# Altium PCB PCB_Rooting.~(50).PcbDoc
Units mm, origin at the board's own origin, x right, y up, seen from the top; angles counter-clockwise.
Board outline 68.5 x 51 mm, 4 copper layers (Top Layer, Mid-Layer 1, Mid-Layer 2, Bottom Layer); 59 components, 42 nets, 192 pads, 55 vias.
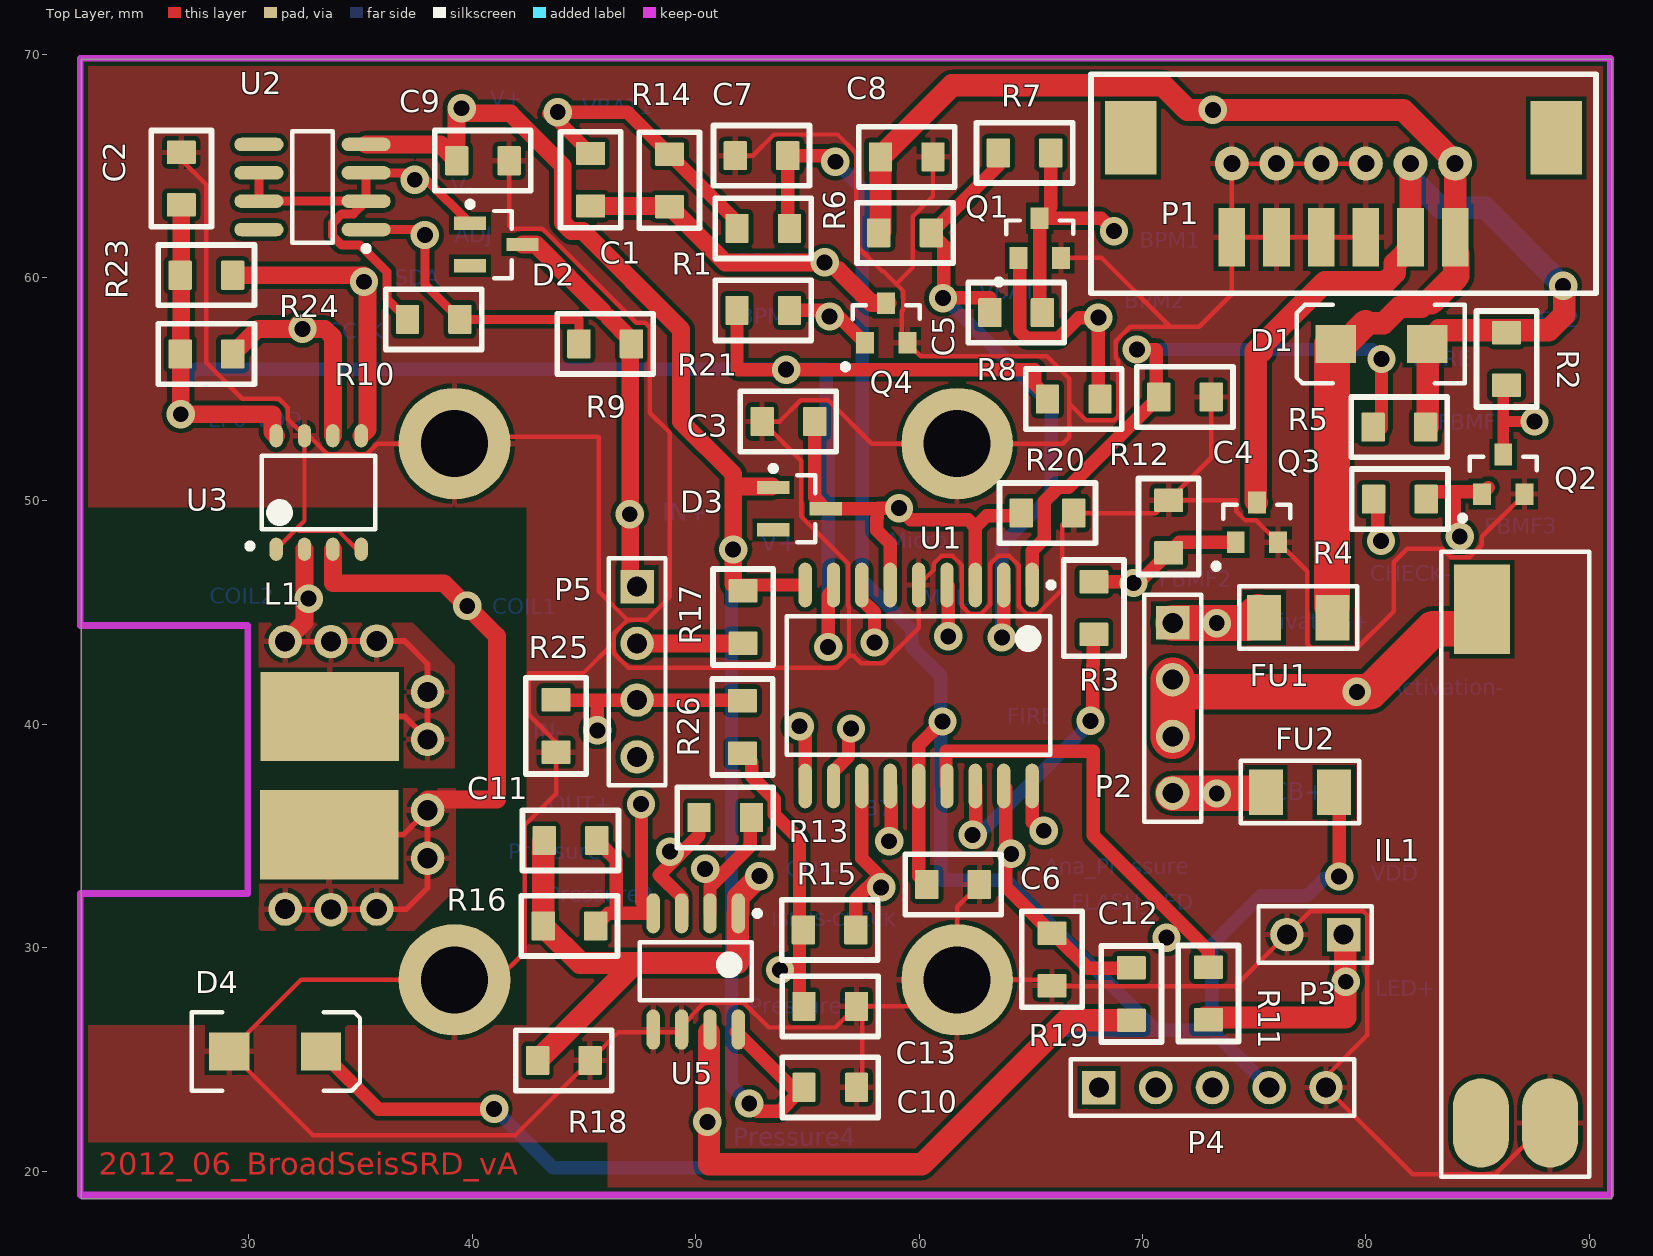
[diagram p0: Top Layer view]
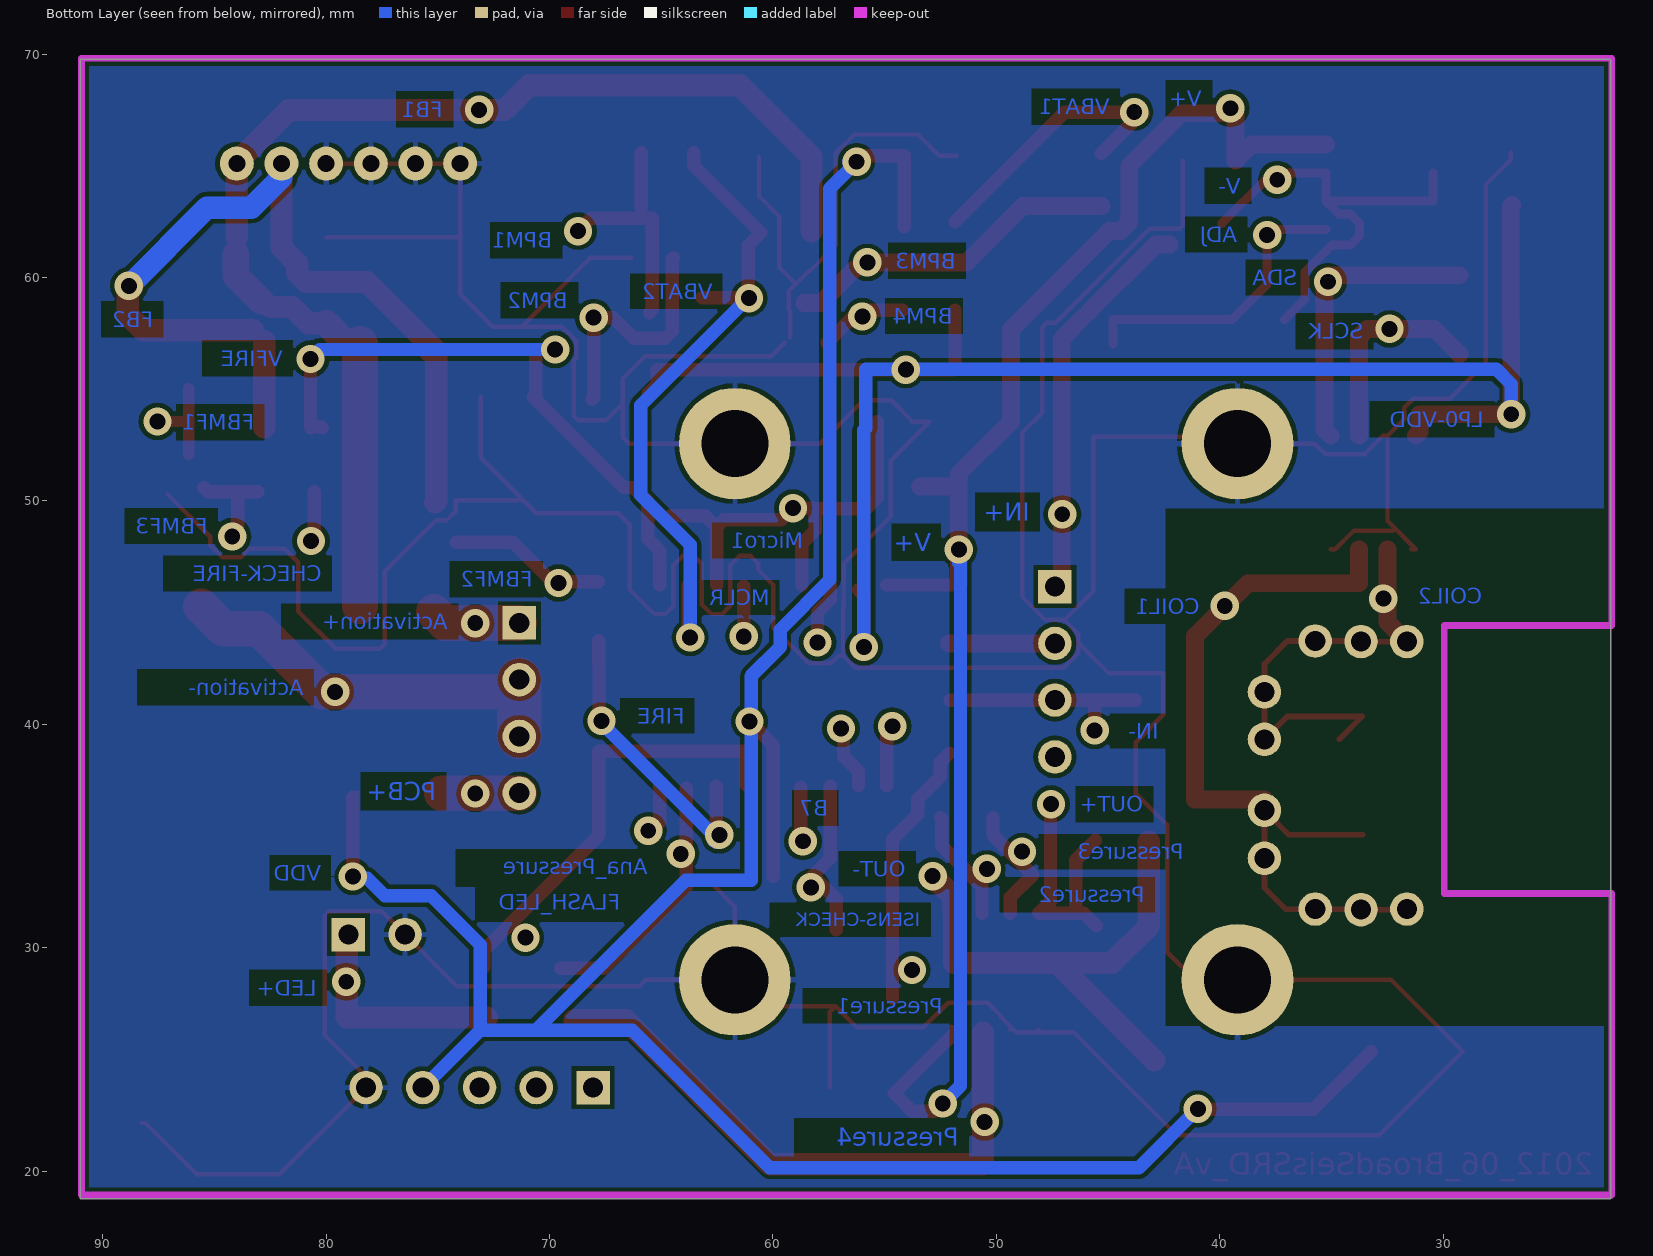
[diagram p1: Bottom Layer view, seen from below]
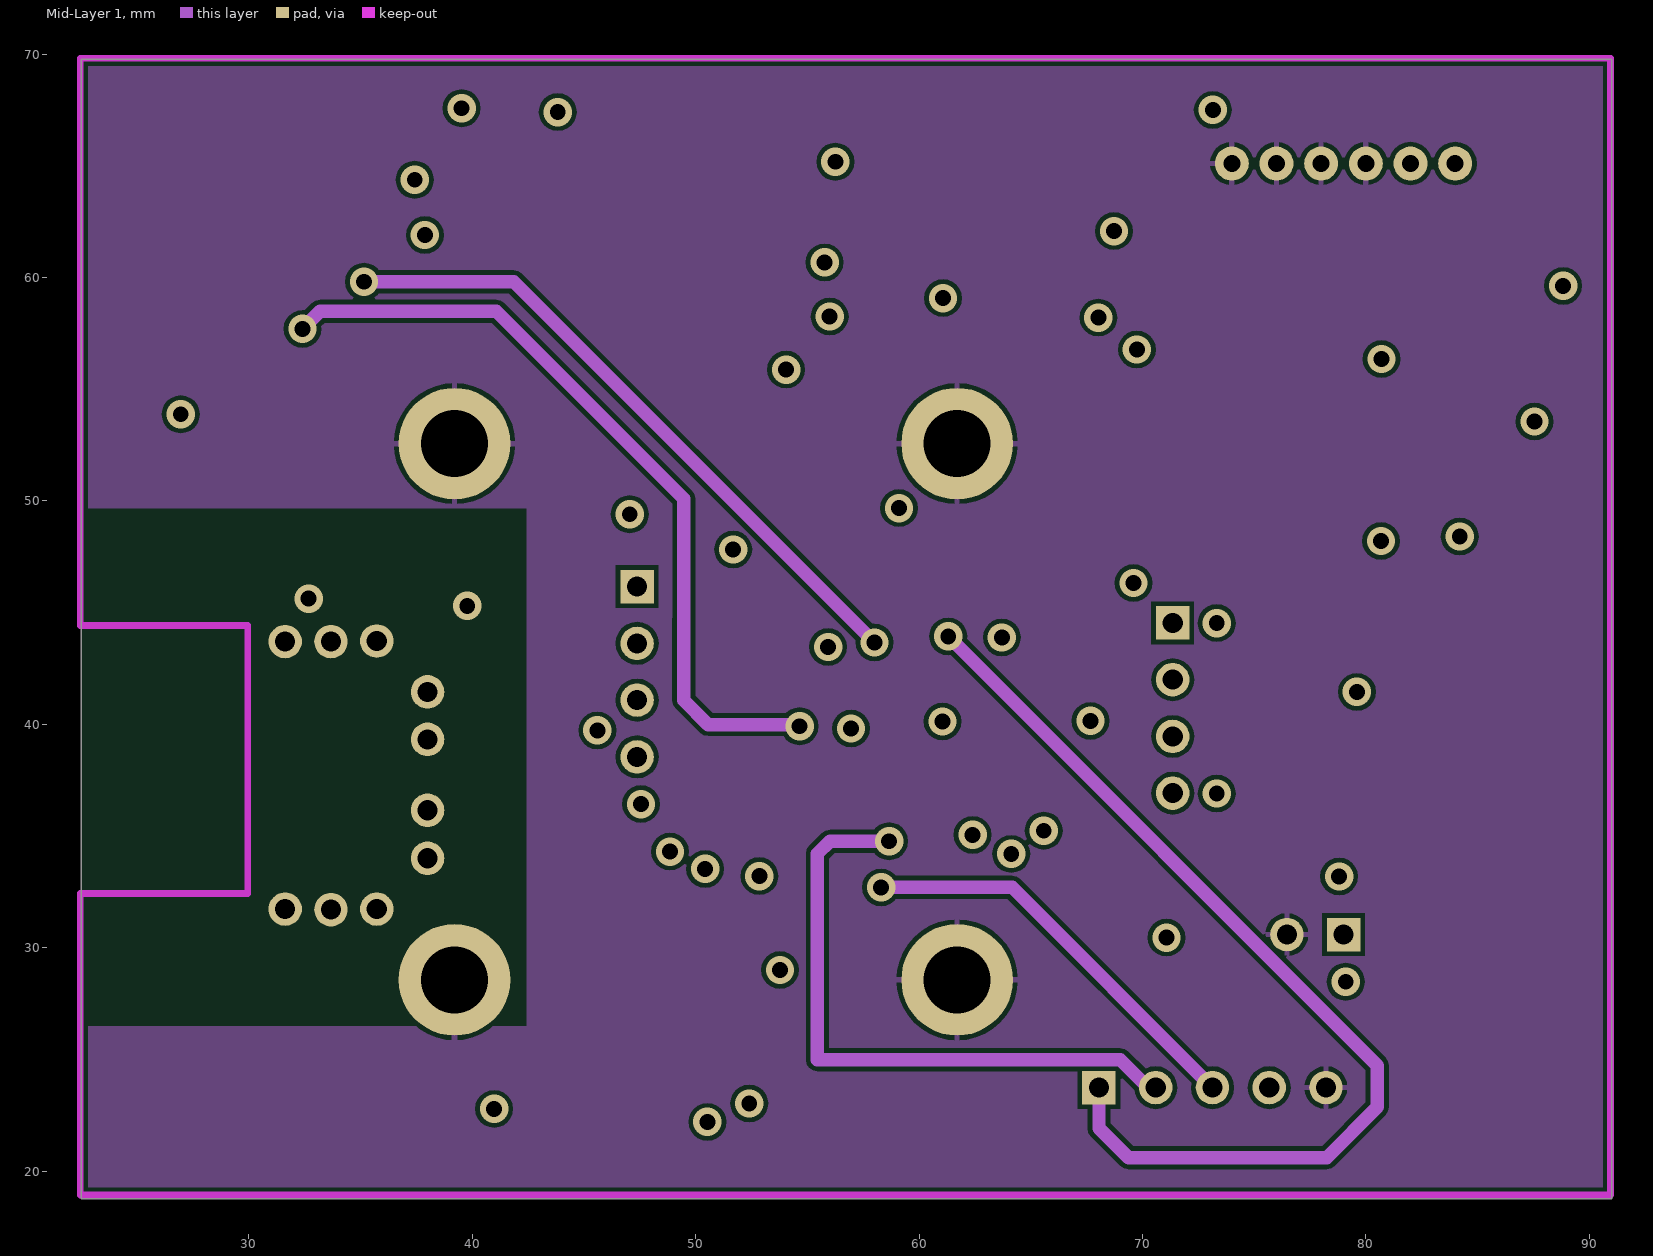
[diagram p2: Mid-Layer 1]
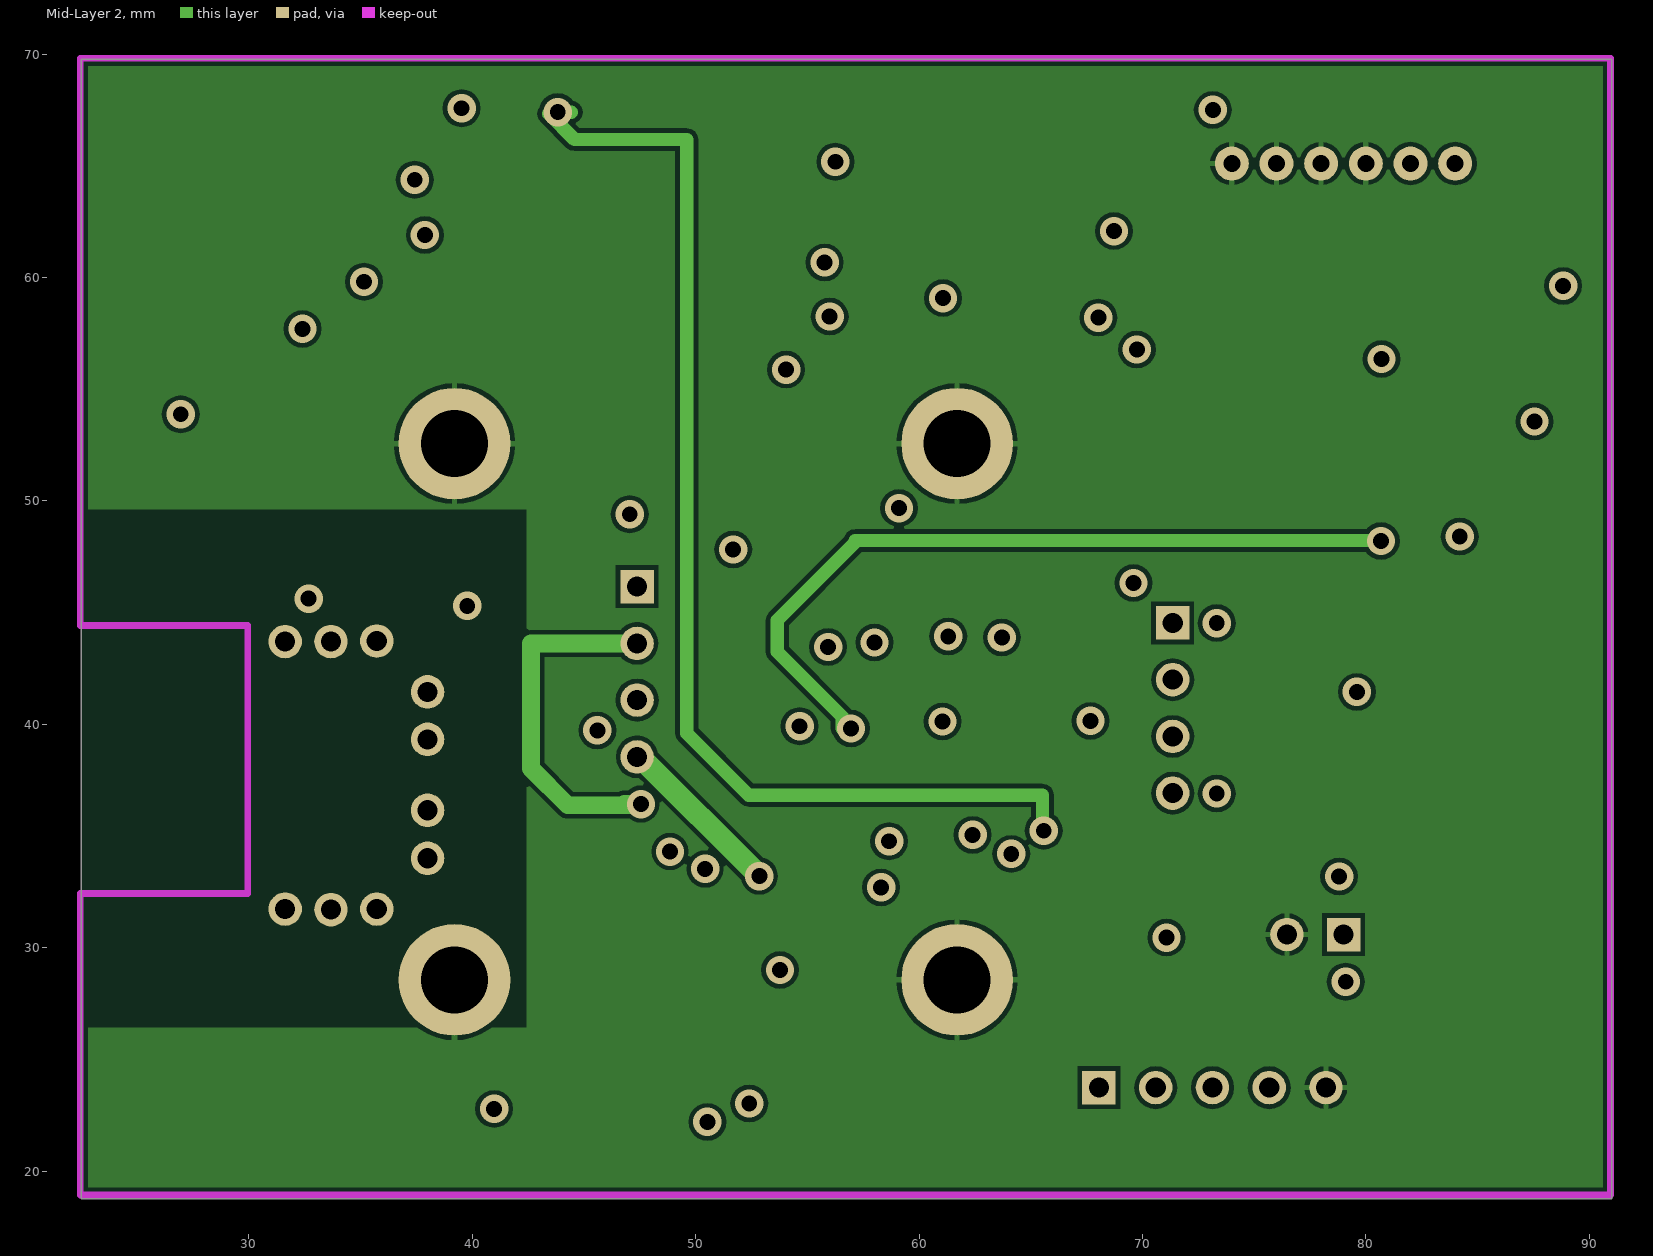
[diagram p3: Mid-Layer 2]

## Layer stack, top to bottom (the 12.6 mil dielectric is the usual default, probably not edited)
Top Layer: signal copper 0.0356
Dielectric: dielectric 0.32, FR-4, Dk 4.8
Mid-Layer 1: signal copper 0.0356
Dielectric: dielectric 0.32, FR-4, Dk 4.8
Mid-Layer 2: signal copper 0.0356
Dielectric: dielectric 0.32, FR-4, Dk 4.8
Bottom Layer: signal copper 0.0356

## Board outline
22.505,18.76 91.005,18.76 91.005,69.76 22.505,69.76

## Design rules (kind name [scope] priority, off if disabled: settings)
Clearance [All] p1: gap=0.2
HoleSize [All] p1: absolutevalues=TRUE maxlimit=5 minlimit=0.025 maxpercent=80.000 minpercent=20.000
PolygonConnect [All] p1: connectstyle=Relief reliefconductorwidth=0.254 reliefentries=4 polygonreliefangle="90 Angle"
RoomDefinition PCB_Schematics [InComponentClass('PCB_Schematics')] p1: confinementstyle=ConfineIn formatcopy=TRUE lockcomponents=FALSE outline 0,0 106.55,0 106.55,84.8 0,84.8
RoutingVias [All] p1: holewidth=0.6 width=1 viastyle="Through Hole" minholewidth=0.711 minwidth=1.27 maxholewidth=0.711 maxwidth=1.27
SilkscreenOverComponentPads [All] p1: minsilkscreentomaskgap=0.254
SolderMaskExpansion [All] p1: expansion=0.102
Width [All] p1: maxlimit=2 minlimit=0.2 preferedwidth=0.6
26 further rules are at their usual default settings.

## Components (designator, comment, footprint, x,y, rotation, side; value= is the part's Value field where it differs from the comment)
C1 "" 1608[0603] 45.3,64.375 r90 top
C2 "" 1608[0603] 26.975,64.425 r270 top
C3 "" 1608[0603] 54.15,53.55 r0 top
C4 "" 1608[0603] 71.9,54.65 r180 top
C5 "" 1608[0603] 64.35,58.425 r180 top
C6 "" 1608[0603] 61.525,32.825 r180 top
C7 "" 1608[0603] 52.95,65.45 r0 top
C8 "" 1608[0603] 59.45,65.4 r180 top
C9 "" 1608[0603] 40.475,65.225 r180 top
C10 "" 1608[0603] 56.025,23.75 r180 top
C11 "" 1608[0603] 44.4,34.8 r0 top
C12 "" 1608[0603] 65.95,29.475 r90 top
C13 "" 1608[0603] 56.025,27.375 r180 top
D1 "" DiodeRS1D(recommendedfootprint) 80.7,57.025 r180 top
D2 "" SOT-23_M 41.075,61.475 r0 top
D3 "" SOT-23_M 54.65,49.65 r0 top
D4 "" DiodeRS1D(recommendedfootprint) 31.175,25.35 r0 top
FU1 "1A" FU(recommendedfootprint) 76.975,44.775 r0 top
FU2 "200mA" FU(recommendedfootprint) 77.055,36.96 r180 top
IL1 "ILS" ILS 88.15,45.15 r270 top
L1 "" INDC4532 33.625,37.7 r270 top
P1 "ConnectorToFB" "HIROSE DF3DZ 6P-2V" 79,63.1 r0 top
P2 "Battery Pack pigtail" HDR1X4 71.355,44.535 r270 top
P3 "Connector to LED" HDR1X2 79.005,30.585 r180 top
P4 "Connector to Prog." HDR1X5 68.055,23.735 r0 top
P5 "Pressure Transducer pigtail" HDR1X4 47.38,46.16 r270 top
Q1 "" transistor_SOT-23(recommendedfootprint) 65.4,61.85 r90 top
Q2 "" transistor_SOT-23(recommendedfootprint) 86.15,51.275 r90 top
Q3 "" transistor_SOT-23(recommendedfootprint) 75.125,49.125 r90 top
Q4 "" transistor_SOT-23(recommendedfootprint) 58.525,58.05 r90 top
R1 "" J1-0603 53.025,62.2 r0 top
R2 "" J1-0603 86.3,56.35 r90 top
R3 "" J1-0603 67.825,45.2 r90 top
R4 "" J1-0603 81.525,50.075 r0 top
R5 "" J1-0603 81.5,53.3 r0 top
R6 "" J1-0603 59.375,62 r180 top
R7 "" J1-0603 64.725,65.575 r180 top
R8 "" J1-0603 66.925,54.55 r0 top
R9 "" J1-0603 45.95,57.025 r0 top
R10 "" J1-0603 38.275,58.125 r180 top
R11 "" J1-0603 72.95,27.95 r90 top
R12 "" J1-0603 71.175,48.85 r270 top
R13 "" J1-0603 51.325,35.825 r0 top
R14 "" J1-0603 48.825,64.35 r90 top
R15 "" J1-0603 56,30.8 r180 top
R16 "" J1-0603 44.35,30.975 r0 top
R17 "" J1-0603 52.125,44.8 r90 top
R18 "" 1608[0603] 44.1,24.95 r180 top
R19 "" J1-0603 69.5,27.925 r90 top
R20 "" J1-0603 65.75,49.45 r180 top
R21 "" J1-0603 53.025,58.525 r0 top
R23 "" J1-0603 28.1,60.1 r0 top
R24 "" J1-0603 28.1,56.575 r180 top
R25 "" J1-0603 43.75,39.925 r90 top
R26 "" J1-0603 52.1,39.875 r90 top
U1 "PIC16LF1827-I/SO" SOIC-SO18_L 59.98,41.735 r270 top
U2 "LM334D" SO8_N 32.85,64.05 r180 top
U3 "M24LR64" SO8N_N 33.125,50.375 r90 top
U5 "AD620BR" R-8D_N 50.005,28.935 r270 top

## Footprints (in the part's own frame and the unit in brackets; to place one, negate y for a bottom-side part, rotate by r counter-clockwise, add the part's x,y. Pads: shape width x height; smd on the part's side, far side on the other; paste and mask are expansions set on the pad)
1608[0603] [mm] "Chip Capacitor, Body 1.6x0.8mm, IPC High Density"
  rrect10% 1.05x1.3 smd: 1(-1.175,0) 2(1.175,0)
  silkscreen extent -2.15,-1.35 2.15,1.35
DiodeRS1D(recommendedfootprint) [mm] "DO-214-AB/SMC; 2 C-Bend Leads; Body 7.9 x 5.9 mm, inc. leads (LxW)"
  rect 1.8x1.7 smd: 1(-2.05,0) 2(2.05,0)
  silkscreen extent -3.73,-1.75 3.8,1.75
FU(recommendedfootprint) [mm] "Thru-Hole; 2 Leads"
  rect 1.52x2.03 smd: 1(-1.525,0) 2(1.525,0)
  silkscreen extent -2.65,-1.4 2.65,1.4
HDR1X2 [mm] "Connector; Header; 2 Position"
  rect 1.5x1.5 hole 0.9: 1(0,0)
  round 1.5 hole 0.9: 2(2.54,0)
  silkscreen extent -1.27,-1.27 3.81,1.27
HDR1X4 [mm] "Connector; Header; 4 Position"
  rect 1.5x1.5 hole 0.9: 1(0,0)
  round 1.5 hole 0.9: 2(2.54,0) 3(5.08,0) 4(7.62,0)
  silkscreen extent -1.27,-1.27 8.89,1.27
HDR1X5 [mm] "Connector; Header; 5 Position"
  rect 1.5x1.5 hole 0.9: 1(0,0)
  round 1.5 hole 0.9: 2(2.54,0) 3(5.08,0) 4(7.62,0) 5(10.16,0)
  silkscreen extent -1.27,-1.27 11.43,1.27
"HIROSE DF3DZ 6P-2V" [mm]
  rect 2.3x3.3 smd: 0(-9.52,3.15) 0(9.52,3.15)
  rect 1.2x2.6 smd: 1(-5,-1.3) 2(-3,-1.3) 3(-1,-1.3) 4(1,-1.3) 5(3,-1.3) 6(5,-1.3)
  round 1.524 hole 0.762: 1(-5,2) 2(-3,2) 3(-1,2) 4(1,2) 5(3,2) 6(5,2)
  silkscreen extent -11.3,-3.8 11.3,6
ILS [mm]
  rect 4x2.5 smd: 1(0,-2.95)
  oval 4x2.5 smd: 2(23,-3) 3(23,0.1)
  silkscreen extent -2.58,-4.77 25.4,1.85
INDC4532 [mm] "Chip Inductor, Body 4.5x3.2mm, IPC High Density"
  round 1.5 hole 0.9: 1(-6.025,2.1) 1(-6,0.05) 1(-6,-2) 1(-3.75,4.375) 1(-1.625,4.375) 2(1.55,4.375) 2(3.7,4.375) 2(5.975,2.1) 2(5.975,-2) 2(6,0.05)
  rect 4x6.2 smd: 1(-2.65,0) 2(2.65,-0.025)
  Top Layer lines w0.254: -6,-2 -6,0.05 -6.025,0.075 -6.025,2.1 -6.025,3.35 -5,4.375 -3.75,4.375 -1.625,4.375 -2.65,3.35 -2.65,0 -1.625,1.025
J1-0603 [mm] "Chip Capacitor, Body 1.6x0.8mm, IPC High Density"
  rrect10% 1.05x1.3 smd: 1(-1.175,0) 2(1.175,0)
  silkscreen extent -2.15,-1.35 2.15,1.35
R-8D_N [mm] "SOIC, 8-Leads, Body 4.9x3.9mm, Pitch 1.27mm, IPC Medium Density"
  oval 1.8x0.6 smd: 1(-2.6,1.905) 2(-2.6,0.635) 3(-2.6,-0.635) 4(-2.6,-1.905) 5(2.6,-1.905) 6(2.6,-0.635) 7(2.6,0.635) 8(2.6,1.905)
  silkscreen extent -2.72,-2.5 1.3,2.88, body extent -2,-2.5 2,2.5, height 2.59
SO8_N [mm] "SOIC, 8-Leads, Body 4.9x3.9mm, Pitch 1.27mm, IPC Medium Density"
  oval 2.2x0.6 smd: 1(-2.4,1.905) 2(-2.4,-0.635) 2(-2.4,0.635) 2(2.4,-0.635) 2(2.4,0.635) 4(-2.4,-1.905) 5(2.4,-1.905) 8(2.4,1.905)
  silkscreen extent -2.53,-2.5 0.9,2.88, body extent -1.95,-2.45 1.95,2.45, height 1.75
SO8N_N [mm] "SOP, 8-Leads, Body 5.3x5.3mm, Pitch 1.27mm, IPC Medium Density"
  oval 1.04x0.6 smd: 1(-2.54,1.905) 2(-2.54,0.635) 3(-2.54,-0.635) 4(-2.54,-1.905) 5(2.54,-1.905) 6(2.54,-0.635) 7(2.54,0.635) 8(2.54,1.905)
  silkscreen extent -2.52,-2.54 1.65,3.2, body extent -2.29,-2.54 2.29,2.54, height 2.13
SOIC-SO18_L [mm] "SOIC, 18-Leads, Body 11.5x7.5mm, Pitch 1.27mm, IPC High Density"
  oval 2x0.6 smd: 1(-4.5,5.08) 2(-4.5,3.81) 3(-4.5,2.54) 4(-4.5,1.27) 5(-4.5,0) 6(-4.5,-1.27) 7(-4.5,-2.54) 8(-4.5,-3.81) 9(-4.5,-5.08) 10(4.5,-5.08) 11(4.5,-3.81) 12(4.5,-2.54) 13(4.5,-1.27) 14(4.5,0) 15(4.5,1.27) 16(4.5,2.54) 17(4.5,3.81) 18(4.5,5.08)
  silkscreen extent -4.62,-5.9 3.1,6.06, body extent -3.8,-5.95 3.8,5.95, height 2.65
SOT-23_M [mm] "SOT23, 3-Leads, Body 2.9x1.3mm, Pitch 0.95mm, Lead Span 2.5mm, IPC Low Density"
  rect 1.45x0.6 smd: 1(-1.175,0.95) 2(-1.175,-0.95) 3(1.175,0)
  silkscreen extent -1.3,-1.5 0.7,1.92, body extent -0.7,-1.5 0.7,1.5, height 1.1
transistor_SOT-23(recommendedfootprint) [mm] "SOT23, 3-Leads, Body 2.9x1.3mm, Pitch 0.95mm, Lead Span 2.5mm, IPC Low Density"
  rect 0.972x0.802 smd: 1(-0.975,0.95) 2(-0.975,-0.95) 3(0.8,0)
  silkscreen extent -2.17,-1.5 0.7,1.95, body extent -0.7,-1.5 0.7,1.5, height 1.1

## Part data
C1 C2 C3 C4 C5 C6 C7 C8 C9 C10 C11 C12 C13: library part "Cap Semi", "Capacitor (Semiconductor SIM Model)"
D1 D4: library part Diode, "Default Diode"
D2 D3: library part "Diode BAS16", "Silicon Switching Diode for High-Speed Switching"
FU1 FU2: library part "Fuse 1", "Fuse"
IL1: "SPDT Subminiature Toggle Switch, Right Angle Mounting, Vertical Actuation"
L1: library part Inductor, "Inductor"
P1: "Header, 6-Pin"
P2 P5: "Header, 4-Pin"
P3: "Header, 2-Pin"
P4: "Header, 5-Pin"
Q1 Q2 Q4: library part NPN, "NPN Bipolar Transistor"
Q3: library part MOSFET-IRLML, "N-Channel MOSFET"
R1 R2 R3 R4 R5 R6 R7 R8 R9 R10 R11 R12 R13 R14 R15 R16 R17 R18 R19 R20 R21 R23 R24 R25 R26: library part Res3, "Resistor"
U1: "EPROM-Based 8-Bit CMOS Microcontroller, 25 Bytes RAM, 4 MHz, 18-Pin SOIC, 3.0 to 5.5V Supply Range, Extended Temperature"
U2: "Three Terminal Adjustable Current Source"
U3: "32 Kbit Serial I²C Bus EEPROM"
U5: "Low-Cost, Low-Power Instrumentation Amplifier"

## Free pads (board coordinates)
  round 5 hole 3: 1(39.205,28.56) 1(39.205,52.56) 1(61.705,28.56) 1(61.705,52.56)

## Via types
v1: diameter 1.27, hole 0.711, Top Layer to Bottom Layer, 55 vias

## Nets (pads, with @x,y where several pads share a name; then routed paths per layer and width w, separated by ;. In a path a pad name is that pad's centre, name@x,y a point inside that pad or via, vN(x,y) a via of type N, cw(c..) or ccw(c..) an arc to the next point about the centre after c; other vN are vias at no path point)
ACTIVATION+: FU1.1 P2.1 | length 4
  Top Layer w1.6: P2.1 74.68,44.535 FU1.1@75.185,45.04
  other v1: 73.325,44.525
ACTIVATION-: IL1.1 P2.2 P2.3 | length 18.6
  Top Layer w0.2: P2.2 71.89,41.46
  Top Layer w1.6: 71.89,41.46 80.185,41.46 83.005,44.28 84.605,44.28 IL1.1@85.6,45.275
  Top Layer w2: P2.3 P2.2
  other v1: 79.6,41.45
ADJ: R9.1 R10.1 U2.1 | length 13.6
  Top Layer w0.4: U2.1 37.635,62.145 v1(37.88,61.9) 37.88,59.695 R10.1 44.76,58.125 ; R9.1 44.775,58.11
ANA_PRESSURE: C12.2 R19.2 U1.17 | length 11.4
  Top Layer w0.2: U1.17 U1.17@63.88,37.145 ; v1@63.88,33.66 v1@63.905,33.685
  Top Layer w0.6: U1.17@63.88,37.145 63.88,33.66 63.88,32.72 C12.2 ; C12.2@66.2,30.45 67.575,29.075 R19.2@69.5,29.075
  other v1: 64.125,34.2
B7: P4.2 U1.13 | length 30.8
  Top Layer w0.2: U1.13 U1.13@58.755,37.19
  Top Layer w0.6: v1(58.659,34.764) 58.659,35.014 58.755,35.11 U1.13@58.755,37.19
  Mid-Layer 1 w0.6: v1(58.659,34.764) 56.014,34.764 55.45,34.2 55.45,24.985 69.012,24.985 70.262,23.735 P4.2
BPM1: C5.1 Q1.3 R7.1 | length 10.3
  Top Layer w0.6: C5.1 65.4,58.55 Q1.3 68.15,62.65 v1(68.725,62.075) ; 65.9,63.15 R7.1
BPM2: Q1.1 R8.2 | length 11.5
  Top Layer w0.6: Q1.1 64.5,60.825 64.5,57.599 64.824,57.275 66.226,57.275 67.151,58.2 v1(68.025,58.2) v1@68.325,58.2 ; v1@68.025,58.4 68.025,54.625 R8.2
BPM3: C1.1 Q4.3 R14.1 | length 14.3
  Top Layer w0.8: C1.1 R14.1@48.8,63.2 ; R14.1 51.325,60.675 v1(55.775,60.675) ; 56.387,60.337 57.875,58.85 Q4.3@58.6,58.85
BPM4: Q4.1 R21.2 | length 4
  Top Layer w0.6: R21.2 56.125,58.525 Q4.1
  other v1: 56,58.25
CHECK-FIRE: R4.1 U1.11 | length 40.5
  Top Layer w0.2: v1@56.84,39.695 v1(56.955,39.81)
  Top Layer w0.6: U1.11 56.17,37.9 56.84,38.57 v1@56.84,39.695 ; R4.1@80.525,50.4 80.525,48.225 80.675,48.075 80.675,48.001 80.679,48.001 v1(80.679,48.202)
  Mid-Layer 2 w0.6: v1@56.565,39.81 56.565,40.335 53.65,43.25 53.65,44.65 57.15,48.15 57.15,48.225 80.525,48.225 80.675,48.075 80.675,48.001 80.679,48.001 v1(80.679,48.202)
COIL1: L1.2 U3.3 | length 35.4
  Top Layer w0.254: L1.2@31.65,31.7 L1.2@33.675,31.7 ; L1.2@33.6,35.05 36.9,35.05 38,36.15 38,34 38,32.675 37.05,31.725 35.725,31.725 L1.2@33.7,31.725
  Top Layer w0.6: L1.2@31.625,31.725 L1.2@31.65,31.7 ; L1.2@33.675,31.7 L1.2@33.7,31.725
  Top Layer w0.8: U3.3 33.76,46.31 38.735,46.31 41.1,43.945 41.1,36.625 L1.2@38,36.625
  other v1: 39.775,45.3
COIL2: L1.1 U3.2 | length 4.5
  Top Layer w0.8: L1.1@31.625,43.7 32.49,44.565 U3.2
  other v1: 32.675,45.625
FB1: C8.2 D1.2 FU1.2 P1.6 R6.2 | length 53.6
  Top Layer w1: R6.2@58.275,62.075 C8.2 61.475,68.6 70.92,68.6 72.02,67.5 v1(73.15,67.5) 81.668,67.5 84,65.168 84,65.1 P1.6@84,61.8 ; 79.988,57.95 80.794,57.95 81.519,58.675 82.477,58.675
  Top Layer w1.2: D1.2@79.063,57.025 79.988,57.95 ; 82.91,58.935 84.05,60.075 P1.6@84.05,61.05
  Top Layer w1.6: FU1.2@78.48,45.285 D1.2@78.48,57.025
FB2: D1.1 P1.5 Q3.3 R2.2 R5.2 | length 40.4
  Top Layer w1: Q3.3 75.075,49.975 75.075,56.7 ; 75.335,56.7 75.075,56.7 ; P1.5@82,65.1 82,61.8 82,61.335 81.3,60.635 81.3,60.21 80.89,59.8 78.175,59.8 75.075,56.7 ; R5.2@82.775,53.3 D1.1@82.775,57.15 ; D1.1@83.275,57.635 88.185,57.635 88.875,58.325 v1@88.875,59.65
  Bottom Layer w1: P1.5@82,65.1 82,64.475 83.35,63.125 85.332,63.125 v1(88.832,59.625)
FBMF1: Q2.3 R2.1 | length 4.7
  Top Layer w0.2: Q2.3 Q2.3@86.3,52.225
  Top Layer w0.5: Q2.3 86.15,53.55 ; R2.1@86.15,55.025 86.15,53.55 ; v1@87.725,53.55 86.15,53.55
  other v1: 87.55,53.55
FBMF2: Q3.1 R3.2 R12.2 | length 7.1
  Top Layer w0.6: R3.2 69.875,46.375 R12.2 71.65,48.15 Q3.1
  other v1: 69.6,46.325
FBMF3: Q2.1 R4.2 | length 4.7
  Top Layer w0.6: R4.2@83.05,50.4 83.925,50.4 ; v1(84.204,48.402) 84.254,48.402 84.257,48.405 84.257,48.568 83.95,48.875 83.95,50.375 83.925,50.4 ; Q2.1@85.475,50.6 85.275,50.4 83.925,50.4
FIRE: R3.1 U1.16 | length 14.5
  Top Layer w0.2: U1.16 U1.16@62.53,37.225
  Top Layer w0.6: v1(62.4,35.05) 62.49,35.05 62.58,34.96 62.58,34.86 62.655,34.785 62.605,34.785 62.53,34.71 U1.16@62.53,37.225 ; v1(67.675,40.15) 67.775,40.25 67.775,42.65 67.805,42.68 R3.1@67.805,43.75
  Bottom Layer w0.6: v1(62.4,35.05) 62.49,35.05 62.58,34.96 v1@67.775,40.155 ; v1@62.53,34.71 62.605,34.785 v1@62.655,34.785
FLASH_LED: R11.2 U1.15 | length 20
  Top Layer w0.2: U1.15@61.205,37.28 U1.15
  Top Layer w0.6: U1.15@61.205,37.28 61.205,38.785 67.805,38.785 67.805,35.02 72.95,29.875 R11.2
  other v1: 71.075,30.45
GND: C2.1 C3.1 C4.1 C6.1 C7.1 C8.1 C9.1 C10.1 C12.1 C13.1 D4.1 IL1.3 P1.1 P1.2 P1.3 P1.4 P3.2 P4.5 pad.1 Q1.2 Q2.2 Q3.2 Q4.2 R12.1 R18.1 R20.1 R25.1 U1.5 U3.1 U3.4 U3.7 U5.5 U5.6 | length 363.8
  Top Layer w0.2: C2.1 26.975,65.275 28.1,64.15 28.1,56.181 29.706,54.575 31.34,54.575 31.75,54.165 31.75,53.655 U3.7 ; U3.1@31.421,47.835 U3.1 32.49,49.105 U3.7 ; 32.241,48.655 34.009,48.655 34.829,47.835 U3.4 ; pad.1@38.08,54.26 39.48,52.86 45.665,52.86 45.665,45.95 46.945,44.67 ; pad.1@38.79,26.913 pad.1@38.79,27.87 ; pad.1@39.205,28.56 32.335,28.56 D4.1 32.865,21.61 41.935,21.61 R18.1 46.545,26.22 U5.5@48.215,26.22 ; pad.1@39.205,52.56 35.744,52.56 35.279,52.095 33.511,52.095 32.691,52.915 U3.7 ; pad.1@39.48,28.56 pad.1@40.45,29.53 ; pad.1@41.11,28.56 42.35,29.8 42.35,35.494 43.75,36.894 R25.1 43.75,39.2 42.525,40.425 42.525,42.275 44.955,42.275 46.33,43.65 ; C9.1 41.65,62.324 41.799,62.175 43.14,62.175 47.34,57.975 47.744,57.975 47.95,57.769 47.95,53.95 48.85,53.05 48.85,45.706 47.814,44.67 46.945,44.67 ; U5.5 U5.5@48.215,26.22 ; U5.6 U5.6@49.305,26.4 ; C7.1 52.556,65.45 53.506,66.4 56.353,66.4 57.188,65.565 57.188,61.444 58.345,60.286 58.4,60.286 58.975,59.711 ; C10.1@57.45,23.75 57.45,27.125 C13.1 ; Q4.2@59.226,57.324 59.226,58.486 59.3,58.56 59.3,59.386 58.975,59.711 ; Q4.2 60.075,56.475 65.725,56.475 66.725,55.475 66.725,52.85 66.435,52.56 pad.1@61.705,52.56 ; pad.1@60.52,27.375 C13.1 ; C8.1 60.625,63.644 59.725,62.744 59.725,60.461 58.975,59.711 ; pad.1@61.705,53.855 pad.1@61.705,52.56 ; C6.1 61.705,31.83 61.705,28.56 65.69,28.56 C12.1 65.975,28.275 74.155,28.275 P3.2 ; Q1.2 68.175,60.875 71.25,57.8 ; 66.766,54.316 67.481,53.6 68.719,53.6 68.925,53.806 68.925,56.278 68.815,56.388 68.815,57.162 69.453,57.8 71.25,57.8 ; C4.1 73.075,51.925 R12.1 ; P3.2@77.081,30.585 P3.2 ; P1.4@80,61.8 78,61.8 76,61.8 P1.1@74,61.8 ; P1.4@80.498,65.1 80,65.1 78,65.1 76,65.1 74,65.1 P1.1@74,61.8 ; Q2.2 85.192,48.392 85.192,48.018 84.641,47.467 83.817,47.467 83.434,47.85 81.85,47.85 81.25,47.25 81.25,45.05 79.575,43.375 77.6,43.375 77.38,43.595 77.38,46.845 Q3.2 75.1,49.125 74.614,49.125 74.2,49.539 74.2,50.025 R12.1 ; IL1.3 88.092,22.15 85.792,19.85 82.1,19.85 P4.5 78.215,24.235 80.055,26.075 80.055,31.459 79.879,31.635 77.515,31.635 P3.2 ; 46.33,43.65 46.33,44.055 46.945,44.67 ; 46.33,43.65 46.33,43.185 46.99,42.525 56.317,42.525 56.865,43.073 ; U5.5@48.215,26.22 49.125,26.22 U5.6@49.305,26.4 ; U5.6@49.305,26.4 49.796,26.891 49.796,26.939 50.391,27.535 52.159,27.535 53.269,26.425 56.25,26.425 C13.1 ; 56.865,43.073 57.07,43.073 57.418,42.725 58.392,42.725 59.98,44.313 U1.5 60.65,46.905 60.65,47.184 61.001,47.535 61.499,47.535 61.905,47.129 61.905,45.301 62.271,44.935 62.769,44.935 63.19,45.356 63.19,47.184 63.541,47.535 64.039,47.535 64.46,47.114 64.46,45.286 64.811,44.935 65.309,44.935 66.405,46.031 66.405,48.93 R20.1 70.6,49.45 R12.1 ; 56.865,43.073 56.865,45.261 56.84,45.286 56.84,47.186 54.725,49.301 54.725,51.8 C3.1 53.756,53.55 54.706,54.5 55.944,54.5 57.884,52.56 pad.1@61.705,52.56 ; 71.25,57.8 72.549,57.8 74,59.251 P1.1@74,61.8
IN+: D2.3 P5.1 R9.2 | length 17.4
  Top Layer w0.8: D2.3 42.85,61.475 45.841,58.484 ; 46.107,58.218 47.075,57.25 47.075,46.465 P5.1
  other v1: 47.05,49.4
IN-: P5.3 R25.2 R26.2 | length 9.7
  Top Layer w0.6: R25.2@43.77,41.08 45.55,41.08 ; v1(45.6,39.725) 45.6,41.03 45.55,41.08 ; R26.2@52.07,41.08 P5.3 45.55,41.08
ISENS_CHECK: P4.3 R15.1 U1.12 | length 25.7
  Top Layer w0.6: R15.1 57.175,32.175 58.225,33.225 57.44,34.01 U1.12
  Mid-Layer 1 w0.6: v1(58.3,32.7) 64.17,32.7 P4.3
LED+: P3.1 R11.1 | length 10
  Top Layer w1: R11.1@72.8,26.875 79.08,26.875 79.08,30.51 P3.1
  other v1: 79.1,28.475
LP0-VDD: C2.2 R8.1 R21.1 R23.1 R24.2 U1.8 U3.8 | length 77.5
  Top Layer w0.2: U1.8@56.17,46.025 U1.8
  Top Layer w0.6: R21.1 51.85,55.925 51.9,55.875 v1(54.05,55.875) 65.175,55.875 65.175,55.225 R8.1@65.575,54.825 ; v1(55.93,43.46) 55.93,45.785 U1.8@56.17,46.025
  Top Layer w0.8: C2.2@26.925,63.25 26.975,63.2 26.975,57.925 ; 26.95,57.9 v1(26.95,53.875) 31.05,53.875 31.05,53.085 U3.8
  Bottom Layer w0.6: v1(26.95,53.875) 26.95,55.225 27.61,55.885 55.84,55.885 55.84,53.245 55.93,53.155 v1(55.93,43.46)
MCLR/: P4.1 U1.4 | length 47.1
  Top Layer w0.2: U1.4 U1.4@61.305,46.18
  Top Layer w0.6: v1(61.305,43.935) U1.4@61.305,46.18
  Mid-Layer 1 w0.6: v1(61.305,43.935) 80.515,24.725 80.515,22.865 78.25,20.6 69.375,20.6 68.055,21.92 P4.1
MICRO1: C3.2 D3.3 R20.2 U1.3 U1.6 | length 19.7
  Top Layer w0.6: C3.2 55.325,50.15 D3.3 58.14,49.65 ; 58.11,49.209 58.11,48.685 58.71,48.085 U1.6 ; 58.14,49.239 58.14,49.65 ; U1.3 62.52,48.825 ; R20.2@64.575,49.335 63.03,49.335 62.52,48.825 ; 58.14,49.65 58.165,49.675 v1(59.1,49.675) 59.625,49.15 62.195,49.15 62.52,48.825
OUT+: C11.2 P5.2 R16.2 R17.1 U5.4 | length 33.9
  Top Layer w0.6: R16.2 46.085,31.535 46.45,31.535 ; C11.2 46.45,33.925 46.45,31.535 ; v1@47.45,36.429 v1@47.552,36.327 ; v1@47.575,36.427 47.575,32.06 U5.4 46.45,31.535
  Top Layer w0.8: P5.2 52.12,43.62 R17.1
  Mid-Layer 2 w0.8: P5.2 42.625,43.62 42.625,38.025 44.273,36.377 v1@47.502,36.377 ; v1@47.552,36.327 47.45,36.429 46.812,36.429 46.812,36.427 v1(47.552,36.427)
OUT-: C11.1 P5.4 R16.1 R18.2 U5.1 | length 31.3
  Top Layer w1: R18.2 47.285,29.31 ; C11.1@43.175,34.75 R16.1 44.84,29.31 47.285,29.31 ; U5.1@51.88,31.505 51.88,29.31 47.285,29.31 ; U5.1 51.91,32.26 v1(52.85,33.2)
  Mid-Layer 2 w1: P5.4 47.51,38.54 v1(52.85,33.2)
PCB+: FU2.2 P2.4 | length 3.5
  Top Layer w1.6: P2.4 FU2.2@74.825,36.915
  other v1: 73.325,36.9
PRESSURE1: C13.2 R15.2 R26.1 | length 12.9
  Top Layer w0.6: R26.1 52.502,38.298 52.502,37.674 53.525,36.651 53.525,35.975 54.65,34.85 54.65,28.95 ; v1(53.775,29) 54.6,29 54.65,28.95 ; C13.2@54.65,27.725 54.65,28.95
PRESSURE2: R13.2 U5.2 | length 5.1
  Top Layer w0.6: U5.2 50.64,32.74 52.45,34.55 52.45,35.775 R13.2
  other v1: 50.425,33.525
PRESSURE3: R13.1 U5.3 | length 5.4
  Top Layer w0.6: U5.3 49.37,32.255 48.375,33.25 50.15,35.025 R13.1
  other v1: 48.85,34.3
PRESSURE4: R19.1 U5.7 | length 26.9
  Top Layer w1: U5.7@50.596,26.201 50.596,20.3 60.125,20.3 66.575,26.75 R19.1@68.875,26.75
  other v1: 50.525,22.2
SCLK: R24.1 U1.10 U3.6 | length 48.5
  Top Layer w0.6: v1(54.655,39.91) 54.9,39.665 U1.10
  Top Layer w0.8: R24.1 30.4,57.7 v1(32.4,57.7) ; v1@32.2,57.9 v1(32.4,57.7) ; U3.6 33.76,57.335 33.395,57.7 v1(32.4,57.7)
  Mid-Layer 1 w0.6: v1(32.4,57.7) 33.185,58.485 41.08,58.485 49.475,50.09 49.475,44.55 49.472,44.547 ; 49.472,44.753 49.472,44.547 ; v1@54.855,39.985 50.555,39.985 49.472,41.068 49.472,44.547
SDA: R23.2 U1.7 U3.5 | length 45.2
  Top Layer w0.6: U1.7 57.44,45.575 58.005,45.01 v1(58.005,43.66)
  Top Layer w0.8: R23.2 35.165,60.1 35.305,59.96 35.305,53.19 U3.5
  Mid-Layer 1 w0.6: v1(35.155,59.81) 41.855,59.81 v1@57.755,43.91
V+: C9.2 C10.2 D3.1 R17.2 U1.9 U2.4 U5.8 | length 73.6
  Top Layer w0.2: R17.2@51.68,46.285 R17.2@51.73,46.235 ; U5.8@51.812,26.238 U5.8 U5.8@52.025,26.45 ; v1(52.4,23.025) v1@52.75,22.675
  Top Layer w0.6: R17.2@51.73,46.235 U1.9 ; U5.8@51.812,26.238 54.575,23.475 53.775,22.675 v1@52.75,22.675
  Top Layer w0.8: U2.4 38.57,65.955 C9.2 v1@39.3,67.35 ; v1(39.525,67.575) v1@39.3,67.35 ; R17.2@51.68,46.285 v1(51.68,47.825) 51.68,50.65 ; D3.1@53.425,50.65 51.68,50.65 ; v1@39.3,67.35 41.703,67.35 44.05,65.003 44.05,62.457 44.432,62.075 44.95,62.075 49.35,57.675 49.35,53.54 51.68,51.21 51.68,50.65
  Bottom Layer w0.6: v1(51.68,47.825) 51.68,47.23 51.65,47.2 51.65,48.115 51.605,48.16 51.605,23.82 v1(52.4,23.025)
V-: D2.1 R10.2 U2.2 | length 20.6
  Top Layer w0.4: U2.2@30.45,64.685 30.45,63.415 U2.2@35.25,63.415 ; R10.2 36.19,59.035 36.19,60.239 34.984,61.445 34.16,61.445 33.75,61.855 33.75,62.435 34.16,62.845 34.68,62.845 U2.2@35.25,63.415 ; v1@37.115,64.685 35.25,64.685 U2.2@35.25,63.415 ; v1(37.425,64.375) 37.95,64.375 D2.1
VBAT1: C1.2 R1.1 R14.2 U1.18 | length 69
  Top Layer w0.6: v1(43.827,67.403) v1@44.207,67.403 ; C1.2 43.525,67.325 43.425,67.325 43.5,67.4 44.207,67.4 v1@44.207,67.403 ; R1.1@51.85,62.5 R14.2 46.947,67.403 v1@44.207,67.403 ; U1.18 65.06,35.605 v1@65.28,35.385
  Mid-Layer 2 w0.6: v1(65.58,35.235) 65.525,35.29 65.525,36.825 52.375,36.825 49.6,39.6 49.6,66.175 44.575,66.175 43.425,67.325 43.5,67.4 v1@43.83,67.4 ; v1@43.83,67.4 v1@44.207,67.4 ; v1@43.83,67.4 v1(43.827,67.403) v1@44.207,67.403 ; v1@44.207,67.4 v1@44.207,67.403 ; v1@44.207,67.4 44.432,67.4 44.432,67.403 v1@44.207,67.403
VBAT2: C5.2 R6.1 R7.2 U1.2 | length 30.5
  Top Layer w0.6: 63.175,59.1 61.1,59.1 61.1,61.45 R6.1 63.55,65 R7.2 ; v1(63.705,43.885) 63.79,43.97 U1.2
  Bottom Layer w0.6: v1@61.1,59.1 65.925,54.275 65.925,50.25 63.705,48.03 v1(63.705,43.885)
  other v1: 61.075,59.075
VDD: C6.2 C7.2 D4.2 FU2.1 P4.4 R1.2 U1.14 | length 121.7
  Top Layer w0.2: v1@40.955,22.76 v1(40.98,22.785) ; U1.14 U1.14@60.08,37.135 ; FU2.1 FU2.1@78.805,36.735
  Top Layer w0.6: D4.2 35.815,22.76 v1@40.955,22.76 ; R1.2@54.125,62.275 C7.2 v1@55.981,65.45 ; v1(56.253,65.178) v1@56.33,65.178 ; C6.2@59.98,33.195 U1.14 59.98,39.055 v1(61.05,40.125) ; v1(78.805,33.185) FU2.1@78.805,36.735
  Bottom Layer w0.6: v1(40.98,22.785) 43.615,20.15 60.145,20.15 66.305,26.31 70.625,26.31 ; v1@56.603,65.178 v1(56.253,65.178) 57.45,63.981 57.45,46.468 59.68,44.238 59.68,43.46 60.98,42.16 60.98,33.025 63.91,33.025 70.625,26.31 ; P4.4 73.1,26.31 ; 78.155,33.11 77.37,32.325 75.3,32.325 73.1,30.125 73.1,26.31 ; 70.625,26.31 73.1,26.31
VFIRE: C4.2 R5.1 U1.1 | length 28.4
  Top Layer w0.6: U1.1 65.06,47.76 65.6,48.3 65.6,49.976 66.224,50.6 66.675,50.6 C4.2 70.625,54.75 70.625,56.75 70.6,56.775 v1(69.75,56.775) ; R5.1@80.175,53.275 80.2,53.3 R5.1 ; R5.1@80.7,53.275 v1(80.7,56.35)
  Bottom Layer w0.6: v1(69.75,56.775) 80.3,56.775 v1(80.7,56.35)
pads on no net: D2.2 D3.2 IL1.2 P1.0 U2.5 U2.8

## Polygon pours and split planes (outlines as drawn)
GND on Top Layer "Bottom Layer-No Net" (solid, pour order 6): 22.455,69.81 90.955,69.81 90.955,18.925 22.555,18.925 22.455,19.025 22.45,19.03 22.45,26.525 42.45,26.525 42.45,49.725 22.45,49.725
COIL1 on Top Layer "Top Layer-No Net" (solid, pour order 7): 30.45,30.8 30.5,30.75 37.1,30.75 37.4,30.75 39.35,32.7 39.25,32.8 39.25,37.125 30.525,37.125
COIL2 on Top Layer "Top Layer-No Net" (solid, pour order 10): 30.45,44.575 30.475,44.55 37.05,44.55 37.325,44.55 39.125,42.75 39.225,42.65 39.225,38.025 30.6,38.025 30.45,38.175
GND on Mid-Layer 1 "Bottom Layer-No Net" (solid, pour order 8): 22.455,69.81 90.955,69.81 90.955,18.925 90.905,18.975 22.455,18.975 22.455,26.47 22.45,26.475 42.45,26.475 42.45,49.675 22.45,49.675
GND on Mid-Layer 2 "Bottom Layer-No Net" (solid, pour order 10): 22.455,69.81 90.955,69.81 90.955,18.925 22.455,18.925 22.45,18.93 22.45,26.425 42.45,26.425 42.45,49.625 22.45,49.625
GND on Bottom Layer "Bottom Layer-No Net" (solid, pour order 12): 22.455,69.81 90.955,69.81 90.955,18.925 90.905,18.975 22.455,18.975 22.455,26.47 22.45,26.475 42.45,26.475 42.45,49.675 22.45,49.675

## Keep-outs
Keep-Out Layer:
  lines w0.3: 22.455,18.925 90.955,18.925 90.955,69.81 22.455,69.81 22.455,60.36 22.455,52.422 22.455,51.397 22.455,44.425 29.955,44.425 29.955,39.66 29.955,32.425 22.455,32.425 22.455,18.925

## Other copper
Top Layer:
  text "2012_06_BroadSeisSRD_vA" at 23.275,19.825 h1
Bottom Layer:
  text "V+" at 40.8,67.675 h0.7
  text "VBAT1" at 44.925,67.3 h0.7
  text "FB1" at 74.775,67.175 h0.7
  text "V-" at 39.05,63.75 h0.7
  text "ADJ" at 39.225,61.575 h0.7
  text "BPM1" at 69.875,61.325 h0.7
  text "BPM3" at 51.825,60.4 h0.7
  text "SDA" at 36.525,59.65 h0.7
  text "VBAT2" at 62.7,59.025 h0.7
  text "BPM2" at 69.175,58.625 h0.7
  text "BPM4" at 51.95,57.925 h0.7
  text "FB2" at 87.75,57.775 h0.7
  text "SCLK" at 33.575,57.25 h0.7
  text "VFIRE" at 81.95,56.025 h0.7
  text "LP0-VDD" at 28.175,53.3 h0.7
  text "FBMF1" at 83.225,53.175 h0.7
  text "IN+" at 48.5,49.1 h0.8
  text "FBMF3" at 85.3,48.525 h0.7
  text "Micro1" at 58.65,47.875 h0.7
  text "V+" at 52.925,47.75 h0.8
  text "CHECK-FIRE" at 80.2,46.4 h0.7
  text "FBMF2" at 70.75,46.15 h0.7
  text "COIL2" at 28.25,45.4 h0.7
  text "MCLR" at 60.15,45.325 h0.7
  text "COIL1" at 40.9,44.925 h0.7
  text "Activation+" at 74.55,44.25 h0.7
  text "Activation-" at 81,41.3 h0.7
  text "FIRE" at 63.95,40.025 h0.7
  text "IN-" at 42.725,39.35 h0.7
  text "PCB+" at 75.075,36.6 h0.8
  text "OUT+" at 43.425,36.075 h0.7
  text "B7" at 57.525,35.9 h0.7
  text "Pressure3" at 41.6,33.95 h0.7
  text "Ana_Pressure" at 65.6,33.275 h0.7
  text "OUT-" at 54.05,33.175 h0.7
  text "VDD" at 80.225,33 h0.7
  text "Pressure2" at 43.35,32.025 h0.7
  text "FLASH_LED" at 66.825,31.7 h0.7
  text "ISENS-CHECK" at 53.4,30.95 h0.6
  text "LED+" at 80.425,27.85 h0.7
  text "Pressure1" at 52.4,27.05 h0.7
  text "Pressure4" at 51.675,21.125 h0.8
